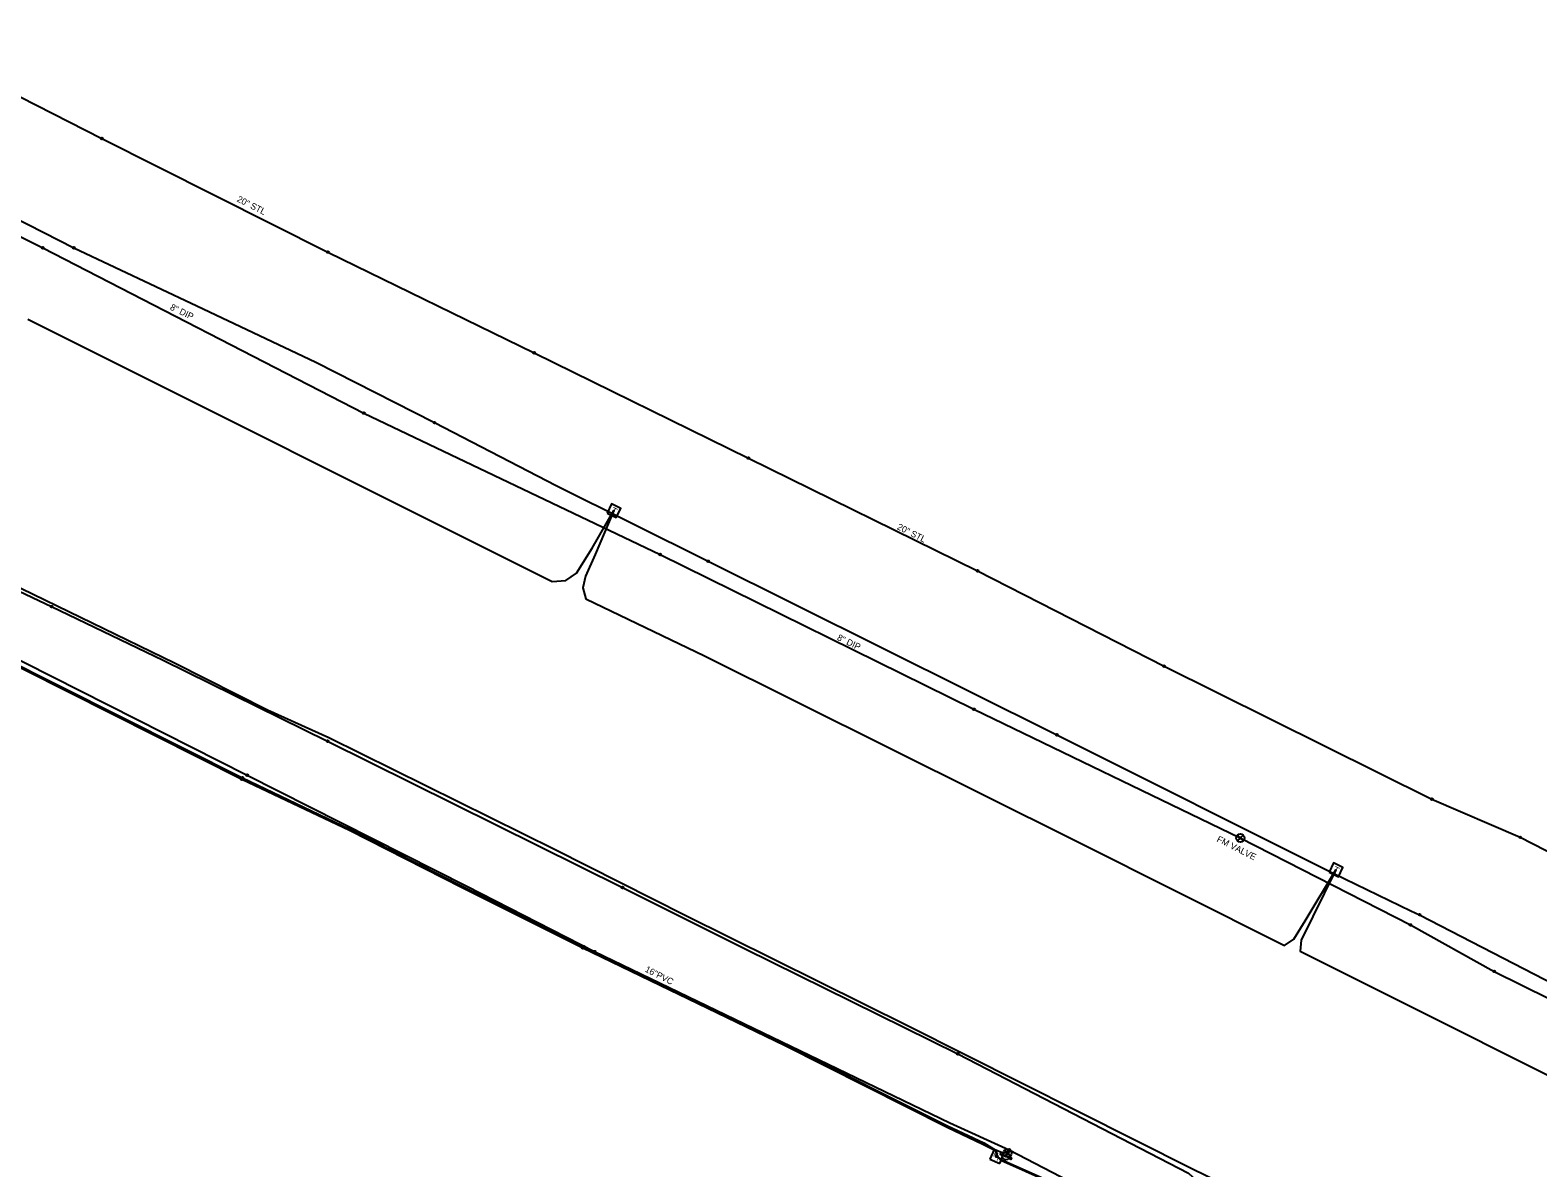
# Model space of a CAD drawing. Extents: x 2244485 to 2250986, y 199568 to 203007.
# Drawn here: x 2249364 to 2250182, y 200045 to 200663 of the extents above; entities that cross this region are included whole.
import ezdxf

# ---------------------------------------------------------------- set-up
doc = ezdxf.new("R2010")
doc.units = 0
for name, color, linetype in [('Default', 7, 'Continuous'), ('Exist Utilities Gas UG Line SUE LOS B', 7, 'Continuous'), ('Exist Utilities Gas UG Line SUE LOS B Text', 7, 'Continuous'), ('Exist Utilities Sanitary Sewer Forced Main SUE LOS B', 7, 'Continuous'), ('Exist Utilities Sanitary Sewer Forced Main SUE LOS B Text', 7, 'Continuous'), ('Exist Utilities Telephone Hand Hole CELL', 7, 'Continuous'), ('Exist Utilities Telephone Pedestal CELL', 7, 'Continuous'), ('Exist Utilities Telephone UG Cable SUE LOS C', 7, 'Continuous'), ('Exist Utilities Telephone UG FO SUE LOS B', 7, 'Continuous'), ('Exist Utilities Telephone UG FO SUE LOS C', 7, 'Continuous'), ('Exist Utilities Water Fire Hydrant CELL', 7, 'Continuous'), ('Exist Utilities Water UG Line SUE LOS B', 7, 'Continuous'), ('Exist Utilities Water UG Line SUE LOS B Text', 7, 'Continuous'), ('Exist Utilities Water Valve CELL', 7, 'Continuous')]:
    doc.layers.add(name, color=color, linetype=linetype)

# ---------------------------------------------------------------- blocks, each defined once
blk = doc.blocks.new('SurveyPointCell')
at = {"layer": 'Default'}
for p, q in [((-0.5, 0), (0.5, 0)), ((0, -0.5), (0, 0.5))]:
    blk.add_line(p, q, dxfattribs=at)
blk.add_circle((0, 0), 0.5, dxfattribs=at)

msp = doc.modelspace()

# ---------------------------------------------------------------- linework, layer by layer
at = {"layer": 'Exist Utilities Gas UG Line SUE LOS B'}
msp.add_lwpolyline([(2249287.36, 200663.03), (2249402.68, 200604.16), (2249525.39, 200542.56), (2249637.28, 200487.84), (2249753.55, 200430.72), (2249877.93, 200369.52), (2249979.08, 200317.76), (2250124.48, 200245.55), (2250172.44, 200224.83), (2250356.61, 200130.32), (2250500.51, 200059.93), (2250689.7, 199967.14), (2250942.93, 199842.48)], dxfattribs=at)
at = {"layer": 'Exist Utilities Sanitary Sewer Forced Main SUE LOS B'}
msp.add_lwpolyline([(2249217.76, 200621.23), (2249370.62, 200544.89), (2249544.88, 200455.15), (2249705.6, 200378.34), (2249875.84, 200294.33), (2250020.48, 200224.47), (2250112.79, 200177.26), (2250158.33, 200152.06), (2250278.35, 200092.68), (2250413.6, 200029.72), (2250577.23, 199946.2), (2250693.93, 199889.36), (2250872.7, 199801.35)], dxfattribs=at)
at = {"layer": 'Exist Utilities Telephone Hand Hole CELL'}
for p, q in [((2249886.83, 200055.32), (2249884.65, 200050.03)), ((2249892.12, 200053.15), (2249886.83, 200055.32)), ((2249884.65, 200050.03), (2249889.95, 200047.85)), ((2249888.39, 200051.59), (2249888.39, 200051.59)), ((2249889.95, 200047.85), (2249892.12, 200053.15))]:
    msp.add_line(p, q, dxfattribs=at)
at = {"layer": 'Exist Utilities Telephone Pedestal CELL'}
for p, q in [((2249680.53, 200402.19), (2249680.53, 200402.19)), ((2250072.34, 200207.23), (2250072.34, 200207.23))]:
    msp.add_line(p, q, dxfattribs=at)
for points in [[(2249676.85, 200400.83), (2249681.88, 200398.39), (2249684.32, 200403.43), (2249679.28, 200405.86), (2249676.85, 200400.83)], [(2250068.67, 200205.84), (2250073.73, 200203.45), (2250076.12, 200208.51), (2250071.06, 200210.9), (2250068.67, 200205.84)]]:
    msp.add_lwpolyline(points, dxfattribs=at)
at = {"layer": 'Exist Utilities Telephone UG Cable SUE LOS C'}
msp.add_lwpolyline([(2249362.52, 200506.1), (2249646.99, 200363.79), (2249654.55, 200364.2), (2249660.21, 200368.21), (2249668.82, 200381.79), (2249680.53, 200402.19), (2249670.32, 200378.35), (2249665.15, 200366.66), (2249663.66, 200360.35), (2249665.38, 200354.32), (2249729.8, 200323.34), (2249931.21, 200222.91), (2250044.46, 200166.15), (2250049.53, 200169.55), (2250055.77, 200179.51), (2250072.34, 200207.23), (2250053.52, 200168.95), (2250052.91, 200163.06), (2250126.32, 200126.28), (2250278.97, 200049.73)], dxfattribs=at)
at = {"layer": 'Exist Utilities Telephone UG FO SUE LOS B'}
for points in [[(2249321.49, 200578.44), (2249387.5, 200544.86), (2249454.17, 200513.32), (2249518.8, 200482.82), (2249583.28, 200449.94), (2249649.27, 200415.89), (2249731.67, 200374.67), (2249920.99, 200280.45), (2250071.25, 200205.24), (2250113.04, 200184.93), (2250117.77, 200182.84), (2250185.79, 200147.71), (2250334.49, 200073.65), (2250524.31, 199986.53), (2250587.45, 199954.07), (2250653.24, 199923.49), (2250715.98, 199890.78), (2250747.66, 199872.18), (2250749.65, 199868.58), (2250760.75, 199866.03), (2250871.46, 199810.27), (2250962.45, 199766.7)], [(2249319.08, 200376.82), (2249375.45, 200350.06), (2249435.96, 200321), (2249525.24, 200277.08), (2249685.23, 200197.6), (2249751.73, 200164.33), (2249867.18, 200107.28), (2249992.37, 200042.44), (2250002.65, 200033.19), (2250015.25, 200027.15), (2250029.09, 200026.7), (2250139.17, 199971.22), (2250192.89, 199945.32), (2250247.36, 199918.05), (2250358.97, 199862.45), (2250517.75, 199783.98), (2250572.3, 199756.11), (2250629.61, 199728.08), (2250729.22, 199678.8), (2250785.25, 199651.26), (2250842.24, 199622.75), (2250880.78, 199603.41)], [(2249313.69, 200339.47), (2249478.6, 200256.38), (2249537.07, 200228.67), (2249598.27, 200197.54), (2249663.63, 200164.83), (2249773.21, 200111.95), (2249861.46, 200067.53), (2249880.8, 200058.34), (2249887.69, 200054.78), (2249888.29, 200051.61), (2249890.49, 200049.61), (2249957.47, 200019.71), (2250041.91, 199978.42), (2250131.82, 199933.16), (2250185.86, 199905.35)], [(2249314.07, 200340.07), (2249478.96, 200257.14), (2249537.25, 200229.25), (2249598.66, 200198.18), (2249664.06, 200165.51), (2249773.44, 200112.37), (2249861.61, 200068.16), (2249881.32, 200059.05), (2249888.07, 200054.88), (2249888.39, 200051.59), (2249888.39, 200051.59), (2249890.69, 200049.91), (2249957.88, 200020.15), (2250042.43, 199979.26), (2250131.9, 199933.91), (2250186.19, 199906.28)]]:
    msp.add_lwpolyline(points, dxfattribs=at)
at = {"layer": 'Exist Utilities Telephone UG FO SUE LOS C'}
msp.add_lwpolyline([(2249352.73, 200362.96), (2249442.05, 200319.48), (2249492.68, 200294.13), (2249525.95, 200279.04), (2249648.71, 200218.15), (2249719.19, 200182.58), (2249840.2, 200122.41), (2249994.21, 200045.08), (2250034.19, 200025.56), (2250090.65, 199997.4), (2250196.48, 199946.19), (2250343.78, 199872.69), (2250476.54, 199806.8), (2250567.69, 199761.35), (2250630.72, 199730.05), (2250730.23, 199680.67), (2250881.91, 199605.67)], dxfattribs=at)
at = {"layer": 'Exist Utilities Water Fire Hydrant CELL'}
msp.add_line((2249893.31, 200051.8), (2249893.31, 200051.8), dxfattribs=at)
for points in [[(2249894.65, 200053.26), (2249895.25, 200054.4), (2249894.34, 200054.87), (2249893.74, 200053.73)], [(2249891.85, 200053.14), (2249890.71, 200053.74), (2249890.24, 200052.83), (2249891.4, 200052.22)], [(2249895.24, 200051.37), (2249896.38, 200050.77), (2249895.91, 200049.86), (2249894.74, 200050.47)]]:
    msp.add_lwpolyline(points, dxfattribs=at)
for radius in [1.98, 0.243]:
    msp.add_circle((2249893.31, 200051.8), radius, dxfattribs=at)
at = {"layer": 'Exist Utilities Water UG Line SUE LOS B'}
msp.add_line((2249895.12, 200055.14), (2249895.12, 200055.14), dxfattribs=at)
for points in [[(2248835.51, 200580.83), (2248922.65, 200537.42), (2249033.15, 200484.25), (2249189.81, 200407.98), (2249240.08, 200380.66), (2249481.52, 200258.57), (2249600.85, 200198.31), (2249670.02, 200162.8), (2249862.82, 200069.86), (2249895.12, 200055.14)], [(2249893.4, 200051.85), (2249894.1, 200053.5), (2249895.12, 200055.14)], [(2249895.12, 200055.14), (2249960.22, 200021.32), (2250046.31, 199980.22), (2250134.08, 199935.34), (2250187.34, 199906.97), (2250250.6, 199876.16), (2250380.36, 199808.54), (2250547.37, 199734.1), (2250673.91, 199668.64), (2250777.46, 199619.82)]]:
    msp.add_lwpolyline(points, dxfattribs=at)
at = {"layer": 'Exist Utilities Water Valve CELL'}
for points in [[(2250022.09, 200226.02), (2250018.94, 200222.87), (2250020.51, 200224.44), (2250022.09, 200222.87), (2250018.94, 200226.02)], [(2249895.72, 200054.96), (2249892.57, 200051.81), (2249894.14, 200053.38), (2249895.72, 200051.81), (2249892.57, 200054.96)]]:
    msp.add_lwpolyline(points, dxfattribs=at)
for centre in [(2250020.51, 200224.44), (2249894.14, 200053.38)]:
    msp.add_circle(centre, 2.23, dxfattribs=at)

# ---------------------------------------------------------------- block references
at = {"layer": 'Default'}
for p in [(2249402.68, 200604.16), (2249370.62, 200544.89), (2249387.5, 200544.86), (2249525.39, 200542.56), (2249637.28, 200487.84), (2249544.88, 200455.15), (2249583.28, 200449.94), (2249753.55, 200430.72), (2249705.6, 200378.34), (2249731.67, 200374.67), (2249877.93, 200369.52), (2249375.45, 200350.06), (2249979.08, 200317.76), (2249875.84, 200294.33), (2249525.24, 200277.08), (2249920.99, 200280.45), (2249481.52, 200258.57), (2249478.6, 200256.38), (2249478.96, 200257.14), (2250124.48, 200245.55), (2250020.48, 200224.47), (2250172.44, 200224.83), (2250071.25, 200205.24), (2249685.23, 200197.6), (2250112.79, 200177.26), (2250117.77, 200182.84), (2249663.63, 200164.83), (2249664.06, 200165.51), (2249670.02, 200162.8), (2250158.33, 200152.06), (2249867.18, 200107.28), (2249895.12, 200055.14), (2249895.12, 200055.14), (2249888.29, 200051.61), (2249888.31, 200051.73), (2249893.4, 200051.85), (2249894.1, 200053.5)]:
    msp.add_blockref('SurveyPointCell', p, dxfattribs=at)

# ---------------------------------------------------------------- texts
at = {"layer": 'Exist Utilities Gas UG Line SUE LOS B Text'}
for p in [(2249475.66, 200570.16), (2249833.9, 200392.26)]:
    msp.add_text('20" STL', height=3.5, rotation=333.09153, dxfattribs=at).set_placement(p)
at = {"layer": 'Exist Utilities Sanitary Sewer Forced Main SUE LOS B'}
msp.add_text('FM VALVE', height=3.5, rotation=333.09153, dxfattribs=at).set_placement((2250007.38, 200222.72))
at = {"layer": 'Exist Utilities Sanitary Sewer Forced Main SUE LOS B Text'}
for p in [(2249439.37, 200511.46), (2249801.34, 200332.08)]:
    msp.add_text('8" DIP', height=3.5, rotation=334.4319, dxfattribs=at).set_placement(p)
at = {"layer": 'Exist Utilities Telephone Hand Hole CELL'}
for p in [(2249886.23, 200051.83), (2249888.06, 200049.5)]:
    msp.add_text('H', height=2.5, rotation=337.66919, dxfattribs=at).set_placement(p)
at = {"layer": 'Exist Utilities Telephone Pedestal CELL'}
for rotation, p in [(334.218, (2249678.76, 200401.14)), (334.68611, (2250070.59, 200206.17))]:
    msp.add_text('T', height=3.42, rotation=rotation, dxfattribs=at).set_placement(p)
at = {"layer": 'Exist Utilities Water UG Line SUE LOS B Text'}
msp.add_text('16"PVC', height=3.5, rotation=333.09153, dxfattribs=at).set_placement((2249697.06, 200152.06))

doc.saveas('drawing.dxf')
